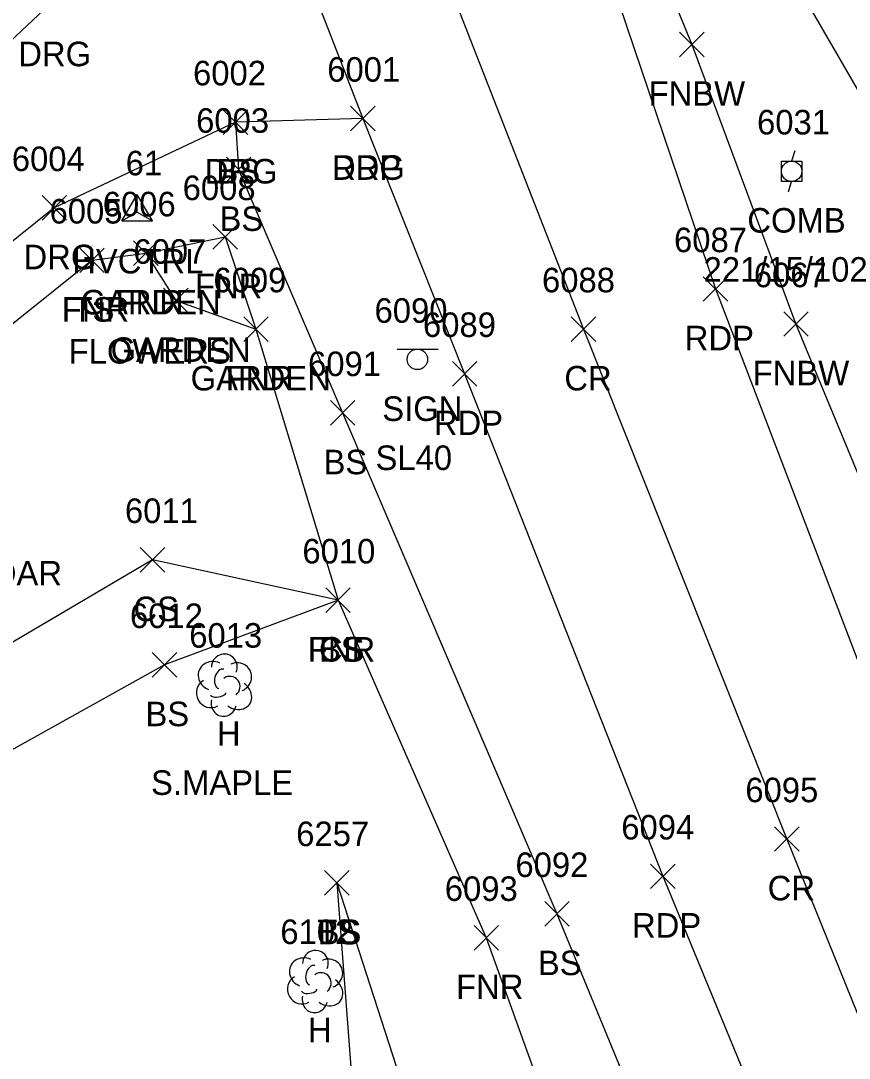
# Model space of a CAD drawing. Extents: x 1472233 to 1475777, y 540726 to 543442.
# Drawn here: x 1472430.6 to 1472498.2, y 541736.5 to 541821 of the extents above; entities that cross this region are included whole.
import ezdxf

# ---------------------------------------------------------------- set-up
doc = ezdxf.new("R2010")
doc.units = 0
for name, color, linetype in [('C_A', 7, 'Continuous'), ('C_I', 7, 'Continuous'), ('CPSM', 7, 'Continuous'), ('L_A', 7, 'Continuous'), ('L_C', 7, 'Continuous'), ('L_I', 7, 'Continuous'), ('L_TIC', 7, 'Continuous'), ('LAPB', 7, 'Continuous'), ('LELB', 7, 'Continuous'), ('LFNC', 7, 'Continuous'), ('LTD', 7, 'Continuous'), ('P_A', 7, 'Continuous'), ('P_I', 7, 'Continuous'), ('P_TIC', 7, 'Continuous'), ('PET', 7, 'Continuous'), ('PRC', 7, 'Continuous'), ('R_A', 7, 'Continuous'), ('R_I', 7, 'Continuous'), ('R_TIC', 7, 'Continuous'), ('RDG', 7, 'Continuous'), ('S_A', 7, 'Continuous'), ('S_C', 7, 'Continuous'), ('S_I', 7, 'Continuous'), ('SSGN', 7, 'Continuous'), ('U_A', 7, 'Continuous'), ('U_C', 7, 'Continuous'), ('U_I', 7, 'Continuous'), ('UP', 7, 'Continuous')]:
    doc.layers.add(name, color=color, linetype=linetype)

msp = doc.modelspace()

# ---------------------------------------------------------------- linework, layer by layer
at = {"layer": 'CPSM'}
for p, q in [((1472438.832, 541804.701), (1472440.082, 541806.866)), ((1472441.332, 541804.701), (1472440.082, 541806.866)), ((1472440.083, 541805.422), (1472440.082, 541806.866)), ((1472438.832, 541804.701), (1472440.083, 541805.422)), ((1472440.083, 541805.422), (1472440.083, 541805.422)), ((1472440.083, 541805.422), (1472441.332, 541804.701)), ((1472438.832, 541804.701), (1472441.332, 541804.701))]:
    msp.add_line(p, q, dxfattribs=at)
at = {"layer": 'L_TIC'}
for points in [[(1472484.317, 541818.086), (1472486.317, 541820.086)], [(1472486.317, 541818.086), (1472484.317, 541820.086)], [(1472447.097, 541811.754), (1472449.097, 541813.754)], [(1472449.097, 541811.754), (1472447.097, 541813.754)], [(1472447.348, 541807.89), (1472449.348, 541809.89)], [(1472449.348, 541807.89), (1472447.348, 541809.89)], [(1472446.251, 541802.401), (1472448.251, 541804.401)], [(1472448.251, 541802.401), (1472446.251, 541804.401)], [(1472439.785, 541801.077), (1472441.785, 541803.077)], [(1472441.785, 541801.077), (1472439.785, 541803.077)], [(1472439.785, 541801.077), (1472441.785, 541803.077)], [(1472441.785, 541801.077), (1472439.785, 541803.077)], [(1472435.391, 541800.492), (1472437.391, 541802.492)], [(1472437.391, 541800.492), (1472435.391, 541802.492)], [(1472435.391, 541800.492), (1472437.391, 541802.492)], [(1472437.391, 541800.492), (1472435.391, 541802.492)], [(1472442.231, 541797.213), (1472444.231, 541799.213)], [(1472444.231, 541797.213), (1472442.231, 541799.213)], [(1472448.765, 541794.885), (1472450.765, 541796.885)], [(1472450.765, 541794.885), (1472448.765, 541796.885)], [(1472448.765, 541794.885), (1472450.765, 541796.885)], [(1472450.765, 541794.885), (1472448.765, 541796.885)], [(1472492.809, 541795.301), (1472494.809, 541797.301)], [(1472494.809, 541795.301), (1472492.809, 541797.301)], [(1472455.833, 541788.055), (1472457.833, 541790.055)], [(1472457.833, 541788.055), (1472455.833, 541790.055)], [(1472440.328, 541776.081), (1472442.328, 541778.081)], [(1472442.328, 541776.081), (1472440.328, 541778.081)], [(1472455.456, 541772.785), (1472457.456, 541774.785)], [(1472457.456, 541772.785), (1472455.456, 541774.785)], [(1472455.456, 541772.785), (1472457.456, 541774.785)], [(1472457.456, 541772.785), (1472455.456, 541774.785)], [(1472455.456, 541772.785), (1472457.456, 541774.785)], [(1472457.456, 541772.785), (1472455.456, 541774.785)], [(1472441.306, 541767.52), (1472443.306, 541769.52)], [(1472443.306, 541767.52), (1472441.306, 541769.52)], [(1472455.355, 541749.745), (1472457.355, 541751.745)], [(1472457.355, 541749.745), (1472455.355, 541751.745)], [(1472455.355, 541749.745), (1472457.355, 541751.745)], [(1472457.355, 541749.745), (1472455.355, 541751.745)], [(1472473.313, 541747.227), (1472475.313, 541749.227)], [(1472475.313, 541747.227), (1472473.313, 541749.227)], [(1472467.551, 541745.277), (1472469.551, 541747.277)], [(1472469.551, 541745.277), (1472467.551, 541747.277)]]:
    msp.add_lwpolyline(points, dxfattribs=at)
at = {"layer": 'LAPB'}
msp.add_lwpolyline([(1472440.785, 541802.077), (1472443.231, 541798.213), (1472449.765, 541795.885)], dxfattribs=at)
at = {"layer": 'LELB'}
for points in [[(1472484.337, 541840.418), (1472508.515, 541798.696), (1472519.34, 541760.356), (1472543.644, 541727.265), (1472543.236, 541714.999), (1472560.459, 541670.843), (1472572.875, 541630.902), (1472574.193, 541601.925), (1472592.342, 541551.172), (1472612.272, 541501.361), (1472628.637, 541456.141), (1472641.026, 541420.938), (1472653.513, 541391.457), (1472656.792, 541384.967), (1472662.925, 541362.196), (1472669.181, 541346.613), (1472674.205, 541333.47)], [(1472448.097, 541812.754), (1472448.348, 541808.89), (1472456.833, 541789.055), (1472474.313, 541748.227), (1472493.036, 541702.804), (1472494.569, 541702.635), (1472518.001, 541641.77), (1472527.768, 541616.945), (1472533.943, 541611.957), (1472541.348, 541598.757), (1472552.579, 541572.187), (1472569.893, 541532.316), (1472586.676, 541490.501), (1472602.946, 541447.471), (1472614.294, 541413.724), (1472616.337, 541394.529)], [(1472436.391, 541801.492), (1472421.411, 541789.524), (1472401.228, 541772.53), (1472387.568, 541756.153), (1472381.39, 541744.301), (1472376.043, 541721.552), (1472378.297, 541690.008), (1472384.499, 541660.373), (1472385.476, 541622.917), (1472385.225, 541602.047), (1472389.103, 541583.282), (1472392.292, 541571.183), (1472400.004, 541561.87), (1472414.969, 541552.967), (1472430.215, 541550.577), (1472460.47, 541554.643), (1472482.624, 541564.355)], [(1472456.456, 541773.785), (1472441.328, 541777.081), (1472419.974, 541764.524), (1472393.226, 541741.709), (1472387.055, 541722.394), (1472387.861, 541691.003), (1472394.403, 541676.497), (1472412.587, 541665.699), (1472419.922, 541640.116), (1472426.411, 541618.317)], [(1472456.456, 541773.785), (1472442.306, 541768.52), (1472421.926, 541757.203), (1472400.904, 541734.529), (1472398.817, 541718.987), (1472396.131, 541693.56), (1472394.403, 541676.497), (1472408.544, 541657.214), (1472414.256, 541635.96), (1472420.205, 541610.928)], [(1472456.355, 541750.745), (1472468.133, 541714.403), (1472477.981, 541680.268), (1472488.5, 541653.393), (1472491.922, 541627.481), (1472471.349, 541622.246), (1472452.049, 541617.906), (1472420.205, 541610.928)], [(1472456.355, 541750.745), (1472459.339, 541711.408), (1472468.15, 541678.645), (1472475.778, 541649.719), (1472485.45, 541631.36), (1472468.299, 541627.822), (1472447.489, 541623.903), (1472426.411, 541618.317)]]:
    msp.add_lwpolyline(points, dxfattribs=at)
at = {"layer": 'LFNC'}
for points in [[(1472590.996, 541866.276), (1472540.714, 541867.285), (1472494.646, 541865.841), (1472479.41, 541862.636), (1472472.669, 541849.878), (1472485.317, 541819.086), (1472493.809, 541796.301), (1472509.073, 541759.452), (1472524.345, 541720.4), (1472527.815, 541710.862), (1472546.469, 541665.224), (1472562.006, 541628.055)], [(1472436.391, 541801.492), (1472440.785, 541802.077), (1472447.251, 541803.401), (1472449.765, 541795.885), (1472456.456, 541773.785), (1472468.551, 541746.277), (1472485.593, 541698.937), (1472485.509, 541699.297), (1472502.774, 541651.725), (1472506.489, 541641.264)]]:
    msp.add_lwpolyline(points, dxfattribs=at)
at = {"layer": 'LTD'}
for p, q in [((1472447.14, 541766.92), (1472447.14, 541766.92)), ((1472447.14, 541766.92), (1472447.14, 541766.92)), ((1472454.572, 541742.764), (1472454.572, 541742.764)), ((1472454.572, 541742.764), (1472454.572, 541742.764))]:
    msp.add_line(p, q, dxfattribs=at)
for centre in [(1472447.187, 541768.353), (1472454.619, 541744.198)]:
    msp.add_arc(centre, 1.047, 335.52715, 180.95627, dxfattribs=at)
for centre, major_axis, ratio, start_param, end_param in [((1472446.348, 541767.586), (1.21, -0.512), 0.895232, 1.570796, 4.712389), ((1472446.932, 541767.378), (-0.208, -0.792), 0.645439, 3.141593, 6.283185), ((1472448.182, 541767.503), (-1.141, -0.483), 0.949671, 1.570796, 4.712389), ((1472446.057, 541766.211), (0.584, -1.042), 0.959034, 3.141593, 6.283185), ((1472447.64, 541766.753), (-0.5, 0.667), 0.989748, 3.141593, 6.283185), ((1472448.14, 541766.086), (-1.09, 0.792), 0.841452, 1.570796, 4.712389), ((1472447.14, 541765.42), (0.265, 1.061), 0.942809, 1.570796, 4.712389), ((1472446.682, 541766.169), (-0.625, -0.083), 0.423636, 0, 3.141593), ((1472453.78, 541743.431), (1.21, -0.512), 0.895232, 1.570796, 4.712389), ((1472455.614, 541743.348), (-1.141, -0.483), 0.949671, 1.570796, 4.712389), ((1472454.364, 541743.222), (-0.208, -0.792), 0.645439, 3.141593, 6.283185), ((1472453.489, 541742.056), (0.584, -1.042), 0.959034, 3.141593, 6.283185), ((1472455.072, 541742.598), (-0.5, 0.667), 0.989748, 3.141593, 6.283185), ((1472455.572, 541741.931), (-1.09, 0.792), 0.841452, 1.570796, 4.712389), ((1472454.114, 541742.014), (-0.625, -0.083), 0.423636, 0, 3.141593), ((1472454.572, 541741.264), (0.265, 1.061), 0.942809, 1.570796, 4.712389)]:
    msp.add_ellipse(centre, major_axis=major_axis, ratio=ratio, start_param=start_param, end_param=end_param, dxfattribs=at)
at = {"layer": 'P_TIC'}
for points in [[(1472457.476, 541812.052), (1472459.476, 541814.052)], [(1472459.476, 541812.052), (1472457.476, 541814.052)], [(1472486.249, 541798.156), (1472488.249, 541800.156)], [(1472488.249, 541798.156), (1472486.249, 541800.156)], [(1472475.482, 541794.885), (1472477.482, 541796.885)], [(1472477.482, 541794.885), (1472475.482, 541796.885)], [(1472465.783, 541791.243), (1472467.783, 541793.243)], [(1472467.783, 541791.243), (1472465.783, 541793.243)], [(1472492.068, 541753.323), (1472494.068, 541755.323)], [(1472494.068, 541753.323), (1472492.068, 541755.323)], [(1472481.949, 541750.285), (1472483.949, 541752.285)], [(1472483.949, 541750.285), (1472481.949, 541752.285)]]:
    msp.add_lwpolyline(points, dxfattribs=at)
at = {"layer": 'PET'}
for points in [[(1472431.809, 541950.997), (1472434.94, 541942.832), (1472440.191, 541926.307), (1472454.881, 541886.717), (1472470.895, 541847.458), (1472487.249, 541799.156), (1472502.862, 541758.418), (1472521.299, 541713.599), (1472521.809, 541711.245), (1472540.253, 541666.598), (1472555.594, 541628.47), (1472566.435, 541602.128), (1472581.857, 541563.085), (1472587.452, 541548.928), (1472607.289, 541499.122), (1472625.035, 541453.695), (1472638.62, 541419.602), (1472649.942, 541390.39), (1472660.9, 541361.786), (1472670.649, 541335.937), (1472680.314, 541310.926), (1472684.25, 541300.561), (1472697.311, 541267.538), (1472711.092, 541230.886)], [(1472410.423, 541944.749), (1472417.04, 541924.067), (1472429.27, 541890.409), (1472437.031, 541868.87), (1472443.664, 541851.187), (1472458.476, 541813.052), (1472466.783, 541792.243), (1472482.949, 541751.285), (1472501.426, 541706.498), (1472501.819, 541705.185), (1472522.016, 541654.988), (1472538.623, 541615.006), (1472544.846, 541600.279), (1472555.288, 541573.09), (1472571.155, 541534.06), (1472588.208, 541491.282), (1472604.526, 541448.364), (1472617.017, 541415.319), (1472632.481, 541374.101), (1472640.327, 541354.301), (1472653.532, 541321.3), (1472663.395, 541294.75), (1472676.203, 541262.983), (1472690.882, 541224.88)]]:
    msp.add_lwpolyline(points, dxfattribs=at)
at = {"layer": 'PRC'}
msp.add_lwpolyline([(1472420.858, 541948.247), (1472433.465, 541909.927), (1472447.3, 541871.915), (1472463.523, 541829.069), (1472476.482, 541795.885), (1472493.068, 541754.323), (1472510.831, 541710.45), (1472511.847, 541707.672), (1472530.206, 541662.333), (1472546.223, 541622.931), (1472556.774, 541597.055), (1472571.636, 541559.778), (1472578.277, 541543.799), (1472597.238, 541495.811), (1472616.732, 541446.138), (1472628.521, 541416.053), (1472640.352, 541384.782), (1472650.997, 541357.435), (1472663.572, 541324.454), (1472674.031, 541297.855), (1472686.993, 541264.398), (1472700.968, 541228.154)], dxfattribs=at)
at = {"layer": 'R_TIC'}
for points in [[(1472447.097, 541811.754), (1472449.097, 541813.754)], [(1472449.097, 541811.754), (1472447.097, 541813.754)], [(1472457.476, 541812.052), (1472459.476, 541814.052)], [(1472459.476, 541812.052), (1472457.476, 541814.052)], [(1472432.314, 541804.765), (1472434.314, 541806.765)], [(1472434.314, 541804.765), (1472432.314, 541806.765)]]:
    msp.add_lwpolyline(points, dxfattribs=at)
at = {"layer": 'RDG'}
for points in [[(1472443.664, 541851.187), (1472441.122, 541840.862), (1472437.139, 541827.961), (1472432.888, 541822.313), (1472422.112, 541812.207), (1472405.366, 541796.547), (1472387.727, 541780.283), (1472366.614, 541755.489), (1472360.262, 541745.014), (1472354.31, 541736.251), (1472351.736, 541734.008), (1472350.45, 541731.024), (1472333.053, 541724.73), (1472338.858, 541690.593), (1472353.84, 541691.596), (1472358.1, 541689.107), (1472361.8, 541678.978), (1472366.888, 541639.978)], [(1472458.476, 541813.052), (1472448.097, 541812.754), (1472433.314, 541805.765), (1472418.45, 541793.865), (1472396.988, 541775.056), (1472383.579, 541758.581), (1472377.023, 541748.043), (1472369.478, 541723.305), (1472371.476, 541689.861), (1472374.14, 541661.129), (1472378.683, 541621.312), (1472380, 541600.019), (1472383.251, 541579.962), (1472388.389, 541568.427), (1472396.047, 541559.533), (1472413.232, 541549.278), (1472429.514, 541545.681), (1472464.232, 541550.412), (1472485.309, 541561.603)]]:
    msp.add_lwpolyline(points, dxfattribs=at)
at = {"layer": 'SSGN'}
for p, q in [((1472461.281, 541794.254), (1472464.615, 541794.254)), ((1472462.928, 541793.421), (1472462.928, 541793.421))]:
    msp.add_line(p, q, dxfattribs=at)
msp.add_circle((1472462.928, 541793.421), 0.833, dxfattribs=at)
at = {"layer": 'UP'}
for p, q in [((1472493.705, 541810.419), (1472493.455, 541809.586)), ((1472492.622, 541807.919), (1472492.622, 541809.586)), ((1472492.622, 541809.586), (1472494.288, 541809.586)), ((1472494.288, 541809.586), (1472494.288, 541807.919)), ((1472493.455, 541808.752), (1472493.455, 541808.752)), ((1472494.288, 541807.919), (1472492.622, 541807.919)), ((1472493.205, 541807.086), (1472493.455, 541807.919))]:
    msp.add_line(p, q, dxfattribs=at)
msp.add_circle((1472493.455, 541808.752), 0.833, dxfattribs=at)

# ---------------------------------------------------------------- texts
at = {"layer": 'C_A'}
msp.add_text('HVCTRL', height=2, dxfattribs=at).set_placement((1472434.776, 541800.422))
at = {"layer": 'C_I'}
msp.add_text('61', height=2, dxfattribs=at).set_placement((1472439.138, 541808.422))
at = {"layer": 'L_A'}
for s, p in [('FNBW', (1472481.789, 541814.086)), ('BS', (1472446.538, 541807.754)), ('BS', (1472446.789, 541803.89)), ('FNR', (1472444.786, 541798.401)), ('TS', (1472434.8, 541796.492)), ('GARDEN', (1472435.454, 541797.077)), ('FNR', (1472438.32, 541797.077)), ('FNR', (1472433.926, 541796.492)), ('GARDEN', (1472437.9, 541793.213)), ('GARDEN', (1472444.434, 541790.885)), ('FNR', (1472447.3, 541790.885)), ('FNBW', (1472490.282, 541791.301)), ('BS', (1472455.273, 541784.055)), ('CS', (1472439.769, 541772.081)), ('FNR', (1472453.992, 541768.785)), ('CS', (1472454.897, 541768.785)), ('BS', (1472454.897, 541768.785)), ('BS', (1472440.747, 541763.52)), ('H', (1472446.573, 541761.92)), ('TS', (1472454.765, 541745.745)), ('BS', (1472454.796, 541745.745)), ('BS', (1472472.754, 541743.227)), ('FNR', (1472466.087, 541741.277)), ('H', (1472454.005, 541737.764))]:
    msp.add_text(s, height=2, dxfattribs=at).set_placement(p)
at = {"layer": 'L_C'}
for s, p in [('FLOWERS', (1472434.486, 541793.077)), ('M.CEDAR', (1472421.613, 541774.994)), ('S.MAPLE', (1472441.203, 541757.92))]:
    msp.add_text(s, height=2, dxfattribs=at).set_placement(p)
at = {"layer": 'L_I'}
for s, p in [('6002', (1472444.633, 541815.754)), ('6003', (1472444.883, 541811.89)), ('6008', (1472443.786, 541806.401)), ('6006', (1472437.265, 541805.077)), ('6006', (1472437.265, 541805.077)), ('6005', (1472432.926, 541804.492)), ('6005', (1472432.926, 541804.492)), ('6007', (1472439.766, 541801.213)), ('6067', (1472490.376, 541799.301)), ('6009', (1472446.292, 541798.885)), ('6009', (1472446.292, 541798.885)), ('6091', (1472454.014, 541792.055)), ('6011', (1472439.076, 541780.081)), ('6010', (1472453.551, 541776.785)), ('6010', (1472453.551, 541776.785)), ('6010', (1472453.551, 541776.785)), ('6012', (1472439.487, 541771.52)), ('6013', (1472444.321, 541769.92)), ('6257', (1472453.048, 541753.745)), ('6257', (1472453.048, 541753.745)), ('6092', (1472470.927, 541751.227)), ('6093', (1472465.165, 541749.277)), ('6102', (1472451.753, 541745.764))]:
    msp.add_text(s, height=2, dxfattribs=at).set_placement(p)
at = {"layer": 'P_A'}
for s, p in [('RDP', (1472455.965, 541808.052)), ('RDP', (1472484.738, 541794.156)), ('CR', (1472474.915, 541790.885)), ('RDP', (1472464.271, 541787.243)), ('CR', (1472491.501, 541749.323)), ('RDP', (1472480.437, 541746.285))]:
    msp.add_text(s, height=2, dxfattribs=at).set_placement(p)
at = {"layer": 'P_I'}
for s, p in [('6001', (1472455.579, 541816.052)), ('6087', (1472483.864, 541802.156)), ('6088', (1472473.096, 541798.885)), ('6089', (1472463.389, 541795.243)), ('6095', (1472489.682, 541757.323)), ('6094', (1472479.563, 541754.285))]:
    msp.add_text(s, height=2, dxfattribs=at).set_placement(p)
at = {"layer": 'R_A'}
for p in [(1472430.376, 541817.313), (1472445.585, 541807.754), (1472455.965, 541808.052), (1472430.802, 541800.765)]:
    msp.add_text('DRG', height=2, dxfattribs=at).set_placement(p)
at = {"layer": 'R_I'}
for s, p in [('6001', (1472455.579, 541816.052)), ('6002', (1472444.633, 541815.754)), ('6004', (1472429.849, 541808.765))]:
    msp.add_text(s, height=2, dxfattribs=at).set_placement(p)
at = {"layer": 'S_A'}
msp.add_text('SIGN', height=2, dxfattribs=at).set_placement((1472460.066, 541788.401))
at = {"layer": 'S_C'}
msp.add_text('SL40', height=2, dxfattribs=at).set_placement((1472459.515, 541784.401))
at = {"layer": 'S_I'}
msp.add_text('6090', height=2, dxfattribs=at).set_placement((1472459.436, 541796.401))
at = {"layer": 'U_A'}
msp.add_text('COMB', height=2, dxfattribs=at).set_placement((1472489.841, 541803.752))
at = {"layer": 'U_C'}
msp.add_text('221/15/102', height=2, dxfattribs=at).set_placement((1472486.274, 541799.752))
at = {"layer": 'U_I'}
msp.add_text('6031', height=2, dxfattribs=at).set_placement((1472490.636, 541811.752))

doc.saveas('drawing.dxf')
